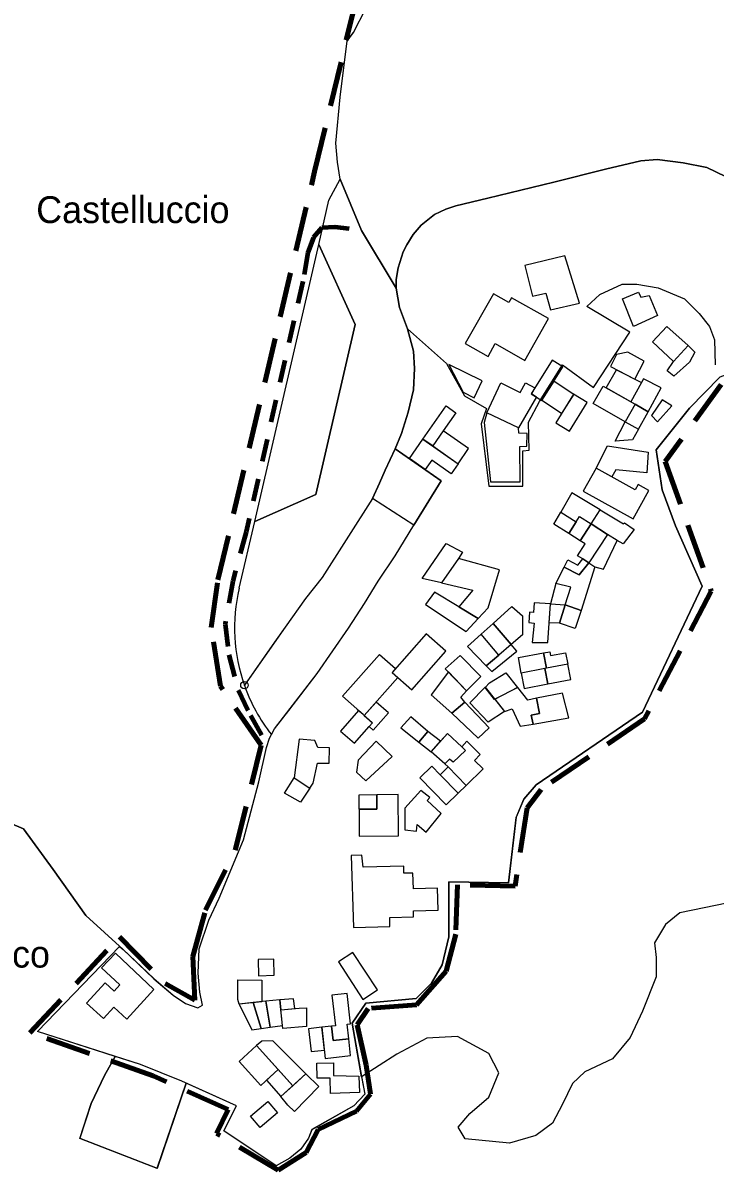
# Model space of a CAD drawing. Extents: x 650468 to 655025, y 889970 to 891591.
# Drawn here: x 654073.7 to 654331.9, y 890519.2 to 890947 of the extents above; entities that cross this region are included whole.
import ezdxf
from ezdxf.enums import TextEntityAlignment as Align

# ---------------------------------------------------------------- set-up
doc = ezdxf.new("R2010")
doc.units = 0
doc.header["$LTSCALE"] = 5.6
doc.header["$PDMODE"] = 32
doc.header["$PDSIZE"] = 2.8
doc.linetypes.add('MEDIUM_DASHED', pattern=[4.5, 3, -1.5])
doc.linetypes.add('SHORT_DASHED', pattern=[2.7, 1.5, -1.2])
for name, color, linetype, lineweight in [('1', 7, 'Continuous', 25), ('16', 7, 'Continuous', 25), ('18', 7, 'Continuous', 25), ('19', 7, 'Continuous', 25), ('35', 7, 'Continuous', 25), ('37', 7, 'Continuous', 25), ('41', 7, 'SHORT_DASHED', 80), ('7', 7, 'MEDIUM_DASHED', 100), ('8', 7, 'Continuous', 25)]:
    doc.layers.add(name, color=color, linetype=linetype, lineweight=lineweight)
doc.layers.add('60', color=7, linetype='Continuous')

msp = doc.modelspace()

# ---------------------------------------------------------------- linework, layer by layer
at = {"layer": '1'}
for p, q in [((654280.53, 890748.26), (654283.45, 890752.76)), ((654280.53, 890748.26), (654283.45, 890752.76)), ((654198.43, 890691.02), (654200.1, 890689.55)), ((654198.43, 890691.02), (654200.1, 890689.55))]:
    msp.add_line(p, q, dxfattribs=at)
for points in [[(654227.28, 890875.62), (654231.47, 890877.58), (654235.24, 890878.82), (654247.17, 890881.6), (654271.8, 890887.66), (654291.02, 890892.47), (654304.19, 890895.57), (654310.24, 890896.03), (654320, 890894.79), (654328.83, 890893.09), (654339.36, 890888.03), (654346.34, 890884.4), (654359.97, 890877.42), (654369.89, 890871.84), (654376.55, 890869.83), (654381.98, 890869.98)], [(654214.18, 890840.86), (654212.94, 890848.08), (654212.94, 890851.38), (654213.7, 890855.72), (654215.53, 890861.63), (654216.86, 890864.21), (654219.27, 890868.13), (654222.21, 890871.61), (654227.28, 890875.62)], [(654219.34, 890810.2), (654219.83, 890818.08), (654219.43, 890824.55), (654217.11, 890832.93), (654214.18, 890840.86)], [(654347.58, 890818.19), (654340.92, 890817.57), (654333.63, 890814.94), (654322.32, 890803.3), (654309.92, 890787.8)], [(654214.91, 890793.93), (654217.37, 890801.83), (654219.34, 890810.2)], [(654165.71, 890680.31), (654167.52, 890683.75), (654172.94, 890690.58), (654183.48, 890704.37), (654195.11, 890721.31), (654201.15, 890730.42), (654206.26, 890738.79), (654212.61, 890748.26), (654219.58, 890759.73), (654229.76, 890776.25), (654212.61, 890788.22), (654214.91, 890793.93)], [(654309.92, 890787.8), (654312.1, 890772.92), (654317.11, 890759.48), (654327.12, 890736.95), (654304.82, 890689.96), (654265.15, 890662.83)], [(654161.69, 890663.96), (654164.58, 890676.78), (654165.71, 890680.31)], [(654140.71, 890580.64), (654139.64, 890585.54), (654139.02, 890592.58), (654139.47, 890601.73), (654143.04, 890612.43), (654146.9, 890620.58), (654156.05, 890642.36), (654161.69, 890663.96)], [(654265.15, 890662.83), (654260.5, 890657.56), (654257.71, 890650.73), (654254.85, 890626.33), (654232.63, 890626.66), (654232.63, 890606.13)], [(654232.63, 890606.13), (654230.12, 890595.67), (654226.09, 890588.86), (654220.36, 890583.12), (654201.59, 890581.46), (654196.55, 890573.94), (654200.04, 890554.01), (654201.19, 890547.5)], [(654177.42, 890526.95), (654173.26, 890523.58), (654168.13, 890520.75), (654148.6, 890533.85), (654153.42, 890543.18), (654132.99, 890552.3), (654117.58, 890558.49), (654079.11, 890570.83), (654109.69, 890602.54), (654111.06, 890601.44), (654122.58, 890590.56), (654129.76, 890584.44)], [(654129.76, 890584.44), (654134.36, 890581.26), (654138.96, 890579.66), (654140.71, 890580.64)], [(654201.19, 890547.5), (654197.12, 890543.11), (654181.45, 890534.24)], [(654181.45, 890534.24), (654180.23, 890531.02), (654177.42, 890526.95)]]:
    msp.add_lwpolyline(points, dxfattribs=at)
for points in [[(654260.96, 890856.56), (654263.82, 890845.13), (654268.8, 890846.23), (654270.45, 890840.05), (654281.26, 890842.47), (654275.89, 890860.09)], [(654310.38, 890837.85), (654301.49, 890833.84), (654297.32, 890844.16), (654303.38, 890846.61), (654304.24, 890844.71), (654307.32, 890845.36)], [(654249.24, 890845.98), (654238.73, 890827.42), (654247.21, 890822.61), (654249.92, 890827.39), (654260.9, 890821.17), (654269.71, 890836.73), (654255.94, 890844.53), (654254.93, 890842.76)], [(654316.42, 890820.73), (654308.6, 890828.06), (654313.9, 890833.85), (654321.81, 890826.65)], [(654313.98, 890817.27), (654316.42, 890820.73), (654321.81, 890826.65), (654324.36, 890824.27), (654322.37, 890820.44), (654316.52, 890815.25)], [(654271.07, 890821.24), (654263.25, 890808.74), (654267.29, 890806.21), (654275.11, 890818.71)], [(654292.83, 890818.83), (654301.98, 890814.13), (654305.41, 890820.81), (654299.29, 890824.21), (654295.12, 890823.3)], [(654232.57, 890819.65), (654237.98, 890809.31), (654242.02, 890807.15), (654244.98, 890813.51)], [(654304.39, 890812.88), (654300.47, 890805.67), (654291.28, 890810.88), (654295.14, 890817.67)], [(654258.57, 890796.04), (654246.72, 890801.56), (654251.94, 890812.75), (654259.23, 890809.15), (654261.22, 890812.75), (654264.67, 890810.95), (654263.35, 890808.84), (654265.32, 890807.52)], [(654267.29, 890806.21), (654271.83, 890813.45), (654279.16, 890808.57), (654274.62, 890801.33)], [(654302.04, 890804.77), (654306.89, 890802.02), (654311.8, 890810.95), (654305.19, 890814.28), (654304.39, 890812.88), (654300.47, 890805.67)], [(654272.5, 890797.92), (654277.53, 890794.78), (654284.15, 890805.4), (654279.13, 890808.53)], [(654290.13, 890811.54), (654302.04, 890804.77), (654298.35, 890798.27), (654286.44, 890805.04)], [(654222.93, 890791.79), (654231.59, 890804.17), (654235.24, 890801.62), (654230.52, 890794.86), (654226.59, 890789.23)], [(654298.35, 890798.27), (654303.31, 890795.45), (654306.89, 890802.02), (654302.04, 890804.77)], [(654298.35, 890798.27), (654303.31, 890795.45), (654306.89, 890802.02), (654302.04, 890804.77)], [(654312.1, 890806.47), (654308.12, 890800.56), (654310.37, 890798.24), (654315.81, 890804.16)], [(654246.72, 890801.56), (654245.77, 890797.97), (654248.15, 890775.84), (654259.22, 890775.84), (654259.05, 890789.03), (654261.7, 890789.16), (654261.77, 890793.93), (654258.72, 890794.05), (654258.57, 890796.04)], [(654301.13, 890791.47), (654294.65, 890791.06), (654298.35, 890798.27), (654303.31, 890795.45)], [(654236.03, 890782.63), (654233.41, 890778.88), (654226.25, 890783.89), (654223.81, 890780.4), (654217.87, 890784.55), (654222.93, 890791.79)], [(654230.52, 890794.86), (654226.59, 890789.23), (654236.03, 890782.63), (654239.96, 890788.27)], [(654287.59, 890780.99), (654291.79, 890789.33), (654306.9, 890786.87), (654306.49, 890779.23), (654294.9, 890780.39), (654293.41, 890777.73)], [(654287.59, 890780.99), (654282.73, 890772.32), (654301.29, 890762.03), (654307.2, 890772.68), (654303.23, 890774.88), (654302.1, 890772.86)], [(654285.66, 890760.15), (654289.01, 890765.43), (654278.46, 890771.74), (654274.3, 890764.5), (654280.01, 890760.89), (654281.29, 890762.91)], [(654301.74, 890758.12), (654297.63, 890752.72), (654295.38, 890754.01), (654291.8, 890756.27), (654285.66, 890760.15), (654289.01, 890765.43), (654297.77, 890760.18), (654298.16, 890760.56)], [(654274.3, 890764.5), (654280.01, 890760.89), (654277.28, 890756.58), (654271.72, 890760.02)], [(654285.66, 890760.15), (654281.61, 890753.9), (654277.28, 890756.58), (654280.01, 890760.89), (654281.29, 890762.91)], [(654291.8, 890756.27), (654284.78, 890745.6), (654282.52, 890747.1), (654280.53, 890748.26), (654283.45, 890752.76), (654281.61, 890753.9), (654285.66, 890760.15)], [(654229.79, 890738.17), (654222.6, 890739.83), (654231.61, 890752.81), (654237.71, 890749.6), (654236.12, 890747.29)], [(654287.03, 890744.1), (654290.21, 890743.33), (654295.38, 890754.01), (654291.8, 890756.27), (654284.78, 890745.6)], [(654229.79, 890738.17), (654241.55, 890735.45), (654236.25, 890729.28), (654243.56, 890724.91), (654247.25, 890728.9), (654251.49, 890743.06), (654236.12, 890747.29)], [(654275.59, 890744.06), (654281.22, 890741.15), (654284.78, 890745.6), (654287.03, 890744.1), (654281.99, 890727.81), (654276.03, 890730), (654278.08, 890736.63), (654272.45, 890737.97)], [(654281.22, 890741.15), (654275.59, 890744.06), (654276.95, 890746.71), (654280.67, 890744.79), (654282.52, 890747.1), (654284.78, 890745.6)], [(654272.45, 890737.97), (654270.46, 890730.38), (654276.03, 890730), (654278.08, 890736.63)], [(654272.45, 890737.97), (654270.46, 890730.38), (654276.03, 890730), (654278.08, 890736.63)], [(654227.24, 890734.68), (654223.84, 890730.12), (654239.04, 890720.02), (654243.56, 890724.91), (654236.25, 890729.28)], [(654249.07, 890723), (654256.12, 890729.35), (654260.09, 890725.88), (654260.09, 890718.8), (654255.85, 890715.2)], [(654264.38, 890730.67), (654264.21, 890727.06), (654262.65, 890727.3), (654262.41, 890723.44), (654264.38, 890723.2), (654263.72, 890715.97), (654269.55, 890715.97), (654270.46, 890730.38)], [(654273.9, 890723.18), (654270.01, 890723.27), (654270.46, 890730.38), (654276.03, 890730)], [(654273.9, 890723.18), (654270.01, 890723.27), (654270.46, 890730.38), (654276.03, 890730)], [(654276.03, 890730), (654281.99, 890727.81), (654279.74, 890721.12), (654273.9, 890723.18)], [(654251.18, 890711.23), (654244.6, 890718.98), (654249.07, 890723), (654255.85, 890715.2)], [(654224.15, 890719.18), (654211.43, 890704.78), (654218.79, 890698.28), (654231.51, 890712.68)], [(654251.18, 890711.23), (654244.6, 890718.98), (654239.55, 890714.43), (654246.51, 890707.27)], [(654251.18, 890711.23), (654246.51, 890707.27), (654248.56, 890705.17), (654257.97, 890712.76), (654255.85, 890715.2)], [(654199.37, 890690.14), (654192.89, 890695.86), (654206.7, 890711.5), (654212.69, 890706.21), (654211.43, 890704.78), (654213.58, 890702.88), (654201.04, 890688.67)], [(654239.16, 890697.85), (654244.49, 890703.27), (654236.8, 890711.12), (654231.21, 890706.08)], [(654268.42, 890706.22), (654259.59, 890704.54), (654258.5, 890710.29), (654267.93, 890712.08), (654269.02, 890706.34)], [(654276.96, 890707.85), (654269.02, 890706.34), (654267.93, 890712.08), (654270.19, 890712.51), (654270.47, 890711.04), (654276.14, 890712.13)], [(654268.42, 890706.22), (654259.59, 890704.54), (654260.69, 890698.79), (654269.52, 890700.49)], [(654276.96, 890707.85), (654269.02, 890706.34), (654268.42, 890706.22), (654269.52, 890700.49), (654278.06, 890702.13)], [(654225.99, 890696.4), (654233.73, 890689.6), (654238.5, 890693.72), (654237.04, 890695.53), (654239.16, 890697.85), (654232.41, 890704.96)], [(654246.07, 890699.18), (654247.73, 890700.85), (654253.82, 890704.58), (654258.25, 890699.1), (654249.64, 890694.73)], [(654246.13, 890699.24), (654253.37, 890690.26), (654247.27, 890686.26), (654240.38, 890693.46)], [(654249.7, 890694.79), (654253.37, 890690.26), (654256.25, 890691.25), (654259.19, 890684.71), (654263.99, 890685.52), (654263.32, 890688.83), (654266.41, 890689.45), (654265.28, 890695.11), (654262.1, 890694.48), (654258.31, 890699.16)], [(654265.28, 890695.11), (654266.41, 890689.45), (654263.32, 890688.83), (654263.99, 890685.52), (654277.34, 890687.79), (654274.96, 890697.05)], [(654201.04, 890688.67), (654204.07, 890685.99), (654202.86, 890684.62), (654204.39, 890683.27), (654210.07, 890689.7), (654205.51, 890693.73)], [(654238.5, 890693.72), (654233.73, 890689.6), (654243.53, 890680.22), (654247.64, 890684.07)], [(654198.92, 890690.59), (654192.15, 890682.91), (654197.33, 890678.35), (654202.86, 890684.62), (654204.1, 890686.02), (654200.59, 890689.12)], [(654224.78, 890682.79), (654218.39, 890688.17), (654214.71, 890684.16), (654221.34, 890678.74)], [(654180.76, 890661.66), (654181.93, 890663.45), (654183.65, 890670.9), (654187.9, 890670.9), (654188.03, 890676.69), (654183.74, 890676.75), (654182.6, 890679.42), (654176.76, 890679.91), (654174.91, 890665.5)], [(654224.78, 890682.79), (654221.34, 890678.74), (654225.99, 890675.14), (654229.52, 890679.11)], [(654229.52, 890679.11), (654232.04, 890681.94), (654237.48, 890677.05), (654238.75, 890675.71), (654234.17, 890671.27), (654232.88, 890672.43), (654231.12, 890670.65), (654225.99, 890675.14), (654232.04, 890681.94)], [(654198.19, 890667.58), (654201.57, 890664.32), (654211.5, 890673.42), (654205.42, 890679.16), (654198.73, 890672.07)], [(654238.75, 890675.71), (654234.17, 890671.27), (654232.88, 890672.43), (654231.12, 890670.65), (654232.39, 890669.54), (654239.07, 890662.63), (654245.44, 890668.79), (654242.12, 890671.91), (654244.24, 890674.22), (654239.33, 890679.11), (654237.48, 890677.05)], [(654229.33, 890666.58), (654226.25, 890669.86), (654221.75, 890665.49), (654231.52, 890655.33), (654236.02, 890659.69)], [(654232.39, 890669.54), (654229.33, 890666.58), (654236.01, 890659.68), (654239.07, 890662.65)], [(654174.91, 890665.5), (654180.76, 890661.66), (654177.26, 890656.36), (654171.3, 890659.7)], [(654199, 890659.01), (654199.06, 890653.73), (654205.78, 890653.81), (654205.72, 890659.09)], [(654205.72, 890659.1), (654205.78, 890653.8), (654199.07, 890653.72), (654199.18, 890643.66), (654213.85, 890643.83), (654213.67, 890659.19)], [(654222.14, 890660.75), (654216.11, 890654.19), (654216.2, 890646.09), (654220.49, 890645.51), (654220.75, 890648.02), (654224.07, 890645.19), (654229.77, 890652.19), (654224.53, 890656.95), (654225.53, 890658.17)], [(654196.2, 890636.53), (654197.07, 890609.69), (654210.61, 890610.04), (654210.53, 890613.37), (654219.43, 890613.6), (654219.37, 890615.84), (654228.62, 890616.09), (654228.4, 890624.28), (654219.36, 890624.04), (654219.2, 890629.94), (654215.82, 890629.85), (654215.75, 890632.56), (654200.66, 890632.17), (654200.09, 890636.6)], [(654108.29, 890600.05), (654103.03, 890594.59), (654109.86, 890588.24), (654107.73, 890585.92), (654104.37, 890589.01), (654097.43, 890581.46), (654103.77, 890575.64), (654107.67, 890579.89), (654112.47, 890575.49), (654122.54, 890586.47)], [(654191.38, 890596.85), (654200.52, 890582.83), (654205.92, 890586.35), (654196.78, 890600.37)], [(654161.5, 890597.71), (654161.63, 890591.67), (654167.47, 890591.8), (654167.34, 890597.84)], [(654162.79, 890581.95), (654154.42, 890581.08), (654153.91, 890582.81), (654153.91, 890590.08), (654162.79, 890589.95)], [(654159.57, 890581.61), (654154.42, 890581.08), (654159.08, 890571.44), (654162.52, 890571.95)], [(654159.57, 890581.61), (654162.52, 890571.95), (654165.97, 890572.45), (654164.37, 890582.11)], [(654164.37, 890582.11), (654165.97, 890572.45), (654170.5, 890573.11), (654169.57, 890582.65)], [(654169.57, 890582.65), (654169.94, 890578.88), (654175.18, 890579.4), (654174.67, 890583.08)], [(654188.97, 890584.34), (654190.25, 890572.95), (654188.84, 890572.88), (654189.43, 890567.5), (654195.22, 890568.13), (654194.62, 890573.58), (654195.86, 890573.72), (654194.6, 890584.97)], [(654169.94, 890578.88), (654176.71, 890579.54), (654179.49, 890579.73), (654179.45, 890572.77), (654170.61, 890571.95)], [(654188.84, 890572.88), (654185.21, 890572.48), (654186.49, 890560.83), (654195.91, 890561.86), (654195.22, 890568.13), (654189.43, 890567.5)], [(654185.21, 890572.48), (654180.25, 890571.87), (654181.18, 890563.38), (654186.15, 890563.91)], [(654185.21, 890572.48), (654180.25, 890571.87), (654181.18, 890563.38), (654186.15, 890563.91)], [(654180.25, 890571.87), (654181.18, 890563.37), (654186.15, 890563.91), (654185.22, 890572.41)], [(654160.82, 890565.68), (654154.39, 890559.72), (654162.5, 890550.72), (654168.93, 890556.68)], [(654160.82, 890565.68), (654174.37, 890550.64), (654179.29, 890555.07), (654166.95, 890567.42), (654162.84, 890567.29)], [(654164.51, 890552.7), (654169.95, 890546.66), (654174.37, 890550.64), (654168.93, 890556.68)], [(654164.51, 890552.7), (654169.95, 890546.66), (654174.37, 890550.64), (654168.93, 890556.68)], [(654199.25, 890548.12), (654188.43, 890547.71), (654188.3, 890553.5), (654183.49, 890553.4), (654183.35, 890559.02), (654189.5, 890559.18), (654189.55, 890554.38), (654198.98, 890554.18)], [(654172.51, 890543.32), (654169.95, 890546.66), (654179.29, 890555.07), (654184.05, 890550.31), (654175.02, 890541.04)], [(654172.51, 890543.32), (654169.95, 890546.66), (654179.29, 890555.07), (654184.05, 890550.31), (654175.02, 890541.04)], [(654158.62, 890539.3), (654165.12, 890544.8), (654168.71, 890540.55), (654162.21, 890535.05)]]:
    msp.add_lwpolyline(points, close=True, dxfattribs=at)
at = {"layer": '16'}
msp.add_lwpolyline([(654219.58, 890759.73), (654204.05, 890769.68), (654206.68, 890775.42), (654208.8, 890780.19), (654212.61, 890788.22), (654229.76, 890776.25)], close=True, dxfattribs=at)
for points in [[(654132.99, 890552.3), (654117.58, 890558.49), (654108.06, 890561.55), (654104.11, 890554.41), (654099.12, 890543.97), (654094.92, 890531.01)], [(654094.92, 890531.01), (654123.75, 890519.82), (654134.64, 890551.56), (654132.99, 890552.3)]]:
    msp.add_lwpolyline(points, dxfattribs=at)
at = {"layer": '18'}
msp.add_lwpolyline([(654197.67, 890834.54), (654183.02, 890771.19), (654160.16, 890761.08), (654184.05, 890864.38)], close=True, dxfattribs=at)
for points in [[(654166.4, 890681.61), (654167.52, 890683.75), (654183.48, 890704.37), (654195.11, 890721.31), (654201.15, 890730.42), (654206.26, 890738.79), (654212.61, 890748.26), (654219.58, 890759.73), (654204.05, 890769.68), (654185.31, 890740.14)], [(654185.31, 890740.14), (654179.11, 890732.3), (654171.5, 890721.68), (654156.34, 890700.02)]]:
    msp.add_lwpolyline(points, dxfattribs=at)
msp.add_arc((654215.65, 890720.46), 62.73, 199.0234, 218.2702, dxfattribs=at)
msp.add_point((654156.34, 890700.02), dxfattribs=at)
at = {"layer": '19'}
msp.add_line((654167.6, 890716.1), (654156.34, 890700.01), dxfattribs=at)
for points in [[(654212.94, 890851.38), (654212.94, 890848.08), (654199.97, 890869.6), (654192.08, 890888.74), (654191.09, 890895.12), (654190.43, 890902.13), (654192.08, 890919.36), (654194.7, 890940.28), (654197, 890943.46), (654201.61, 890952.4)], [(654417.62, 890950.54), (654399.53, 890902.06), (654391.04, 890877.22), (654388.18, 890871.69), (654381.98, 890869.98), (654376.55, 890869.83), (654369.89, 890871.84), (654359.97, 890877.42), (654346.34, 890884.4), (654339.36, 890888.03), (654328.83, 890893.09), (654320, 890894.79), (654310.24, 890896.03), (654304.19, 890895.57), (654291.02, 890892.47), (654271.8, 890887.66), (654247.17, 890881.6), (654235.24, 890878.82), (654231.47, 890877.58)], [(654154.4, 890736.14), (654160.16, 890761.07), (654183.02, 890771.18), (654197.67, 890834.53), (654184.05, 890864.37), (654187.87, 890880.92), (654192.08, 890888.73), (654199.97, 890869.59), (654212.94, 890848.07), (654214.18, 890840.85), (654217.11, 890832.92), (654219.43, 890824.54)], [(654231.47, 890877.58), (654227.28, 890875.62), (654222.21, 890871.61)], [(654222.21, 890871.61), (654219.27, 890868.13), (654216.86, 890864.21), (654215.53, 890861.63)], [(654215.53, 890861.63), (654213.7, 890855.72), (654212.94, 890851.38)], [(654219.43, 890824.54), (654219.83, 890818.07), (654219.34, 890810.19)], [(654219.34, 890810.19), (654217.37, 890801.82), (654214.91, 890793.92), (654212.61, 890788.21), (654208.8, 890780.18), (654206.68, 890775.41), (654204.05, 890769.67), (654185.31, 890740.13)], [(654185.31, 890740.13), (654179.11, 890732.29), (654171.5, 890721.67), (654167.6, 890716.1)]]:
    msp.add_lwpolyline(points, dxfattribs=at)
msp.add_arc((654215.63, 890721.3), 63, 166.3715, 199.754, dxfattribs=at)
at = {"layer": '35'}
msp.add_lwpolyline([(654372.59, 890626.21), (654318.79, 890615.05), (654313.35, 890610.75), (654309.34, 890603.88), (654309.92, 890598.44), (654309.92, 890591.28), (654304.77, 890578.4), (654300.19, 890568.66), (654293.6, 890560.65), (654283.3, 890555.78), (654278.72, 890551.48), (654275, 890543.75), (654271.28, 890536.6), (654264.99, 890532.02), (654255.26, 890529.15), (654238.66, 890530.87), (654236.08, 890535.16), (654240.37, 890540.32), (654247.53, 890546.33), (654251.25, 890555.49), (654247.53, 890562.65), (654235.8, 890568.95), (654224.35, 890568.38), (654213.19, 890562.37), (654200.04, 890554), (654196.55, 890573.93), (654201.59, 890581.45), (654220.36, 890583.11), (654226.09, 890588.85), (654230.12, 890595.66), (654232.63, 890606.12), (654232.63, 890616.39), (654232.63, 890626.65), (654254.85, 890626.32), (654257.71, 890650.72), (654260.5, 890657.55), (654265.15, 890662.82), (654304.82, 890689.95), (654327.12, 890736.94), (654317.11, 890759.47), (654312.1, 890772.91), (654309.92, 890787.79), (654322.32, 890803.29), (654333.63, 890814.93)], dxfattribs=at)
at = {"layer": '37'}
for points in [[(654154.4, 890736.15), (654160.16, 890761.07), (654184.05, 890864.37), (654187.87, 890880.92), (654192.08, 890888.73), (654191.09, 890895.11), (654190.43, 890902.12), (654192.08, 890919.35), (654194.7, 890940.27), (654197, 890943.45), (654201.61, 890952.39), (654189.01, 890960.03), (654162.37, 890950.57), (654152.28, 890979.05), (654174.81, 890986.42), (654182.54, 890982.69), (654170.7, 891003.42)], [(653959.44, 890683.82), (653977.03, 890679.77), (654009.33, 890666.64), (654030.52, 890657.56), (654054.75, 890654.53), (654073.92, 890646.45), (654085.02, 890631.3), (654097.14, 890614.13), (654111.06, 890601.43), (654122.58, 890590.55), (654129.76, 890584.43)], [(654161.69, 890663.95), (654164.58, 890676.77), (654165.71, 890680.3), (654166.4, 890681.61)], [(654140.71, 890580.63), (654139.64, 890585.53), (654139.02, 890592.57), (654139.47, 890601.72), (654143.04, 890612.42), (654146.9, 890620.57), (654156.05, 890642.35), (654161.69, 890663.95)], [(654111.06, 890601.43), (654097.14, 890614.13), (654085.02, 890631.3), (654073.92, 890646.45), (654054.75, 890654.53)], [(654372.59, 890626.21), (654318.79, 890615.05), (654313.35, 890610.75), (654309.34, 890603.88), (654309.92, 890598.44), (654309.92, 890591.28), (654304.77, 890578.4), (654300.19, 890568.66), (654293.6, 890560.65), (654283.3, 890555.78), (654278.72, 890551.48), (654275, 890543.75), (654271.28, 890536.6), (654264.99, 890532.02), (654255.26, 890529.15), (654238.66, 890530.87), (654236.08, 890535.16), (654240.37, 890540.32), (654247.53, 890546.33), (654251.25, 890555.49), (654247.53, 890562.65), (654235.8, 890568.95), (654224.35, 890568.38), (654213.19, 890562.37), (654200.04, 890554), (654201.19, 890547.49)], [(654177.42, 890526.94), (654173.26, 890523.57), (654168.13, 890520.74), (654148.6, 890533.84), (654153.42, 890543.17), (654134.64, 890551.56), (654123.75, 890519.81), (654094.92, 890531), (654099.12, 890543.96), (654104.11, 890554.4), (654108.06, 890561.54), (654079.11, 890570.82), (654109.69, 890602.53), (654111.06, 890601.43)], [(654129.76, 890584.43), (654134.36, 890581.25), (654138.96, 890579.65), (654140.71, 890580.63)], [(654201.19, 890547.49), (654197.12, 890543.1), (654181.45, 890534.23)], [(654181.45, 890534.23), (654180.23, 890531.01), (654177.42, 890526.94)]]:
    msp.add_lwpolyline(points, dxfattribs=at)
for centre, radius, start, end in [((654215.63, 890721.3), 63, 166.3715, 199.754), ((654215.65, 890720.46), 62.73, 199.0264, 218.2702)]:
    msp.add_arc(centre, radius, start, end, dxfattribs=at)
at = {"layer": '41'}
msp.add_lwpolyline([(654195.39, 890870.16), (654190.09, 890870.85), (654185.26, 890870.53), (654182.04, 890866.99), (654180, 890861.45), (654178.14, 890850.6), (654156.95, 890757.21), (654151.99, 890738.82), (654149.1, 890722.76), (654150.53, 890711.37), (654153.99, 890698.12), (654158.55, 890688.68), (654163.7, 890679.54)], dxfattribs=at)
at = {"layer": '7'}
for points in [[(654150.33, 890541.8), (654122.3, 890554.3), (654076.35, 890570.4), (654109.74, 890606.13), (654126.72, 890588.79), (654137.85, 890582.59), (654137.14, 890598.86), (654141.85, 890616.07), (654152.92, 890638.46), (654162.58, 890677.6), (654147.42, 890699.63), (654143.92, 890721.53), (654146.47, 890739.35), (654182.51, 890891.6), (654197.39, 890953.2)], [(654334.19, 890812.15), (654313.32, 890783.38), (654330.48, 890735.12), (654305.6, 890687.5), (654266.96, 890661.1), (654261.78, 890654.26), (654257.3, 890625.03), (654235.86, 890625.5), (654235.15, 890607.11), (654231.64, 890593.4), (654220.48, 890580.85), (654202.55, 890579.45), (654198.36, 890573.31), (654201.7, 890558.31), (654203.35, 890547.46), (654198.16, 890541.1), (654183.79, 890534.26), (654179.31, 890525.77), (654168.95, 890519.17), (654145.86, 890532.85), (654150.33, 890541.8)]]:
    msp.add_lwpolyline(points, dxfattribs=at)
at = {"layer": '8'}
msp.add_lwpolyline([(654339.36, 890888.03), (654328.83, 890893.09), (654320, 890894.79), (654310.24, 890896.03), (654304.19, 890895.57), (654291.02, 890892.47), (654271.8, 890887.66), (654247.17, 890881.6), (654235.24, 890878.82), (654231.47, 890877.58), (654227.28, 890875.62), (654222.21, 890871.61), (654219.27, 890868.13), (654216.86, 890864.21), (654215.53, 890861.63), (654213.7, 890855.72), (654212.94, 890851.38), (654212.94, 890848.08), (654214.18, 890840.86), (654217.11, 890832.93), (654231.75, 890819.94), (654238.44, 890807.98), (654246.57, 890803.2), (654244.66, 890797.46), (654247.53, 890774.25), (654260.2, 890774.25), (654260.2, 890787.41), (654262.59, 890787.65), (654262.35, 890798.17), (654266.42, 890805.83), (654275.02, 890819.46), (654286.5, 890811.09), (654300.12, 890831.66), (654284.11, 890841.23), (654288.89, 890845.78), (654297.26, 890849.61), (654302.75, 890849.61), (654310.64, 890848.17), (654320.45, 890844.1), (654325.95, 890838.61), (654329.77, 890833.82), (654331.69, 890828.8), (654331.93, 890819.47)], dxfattribs=at)

# ---------------------------------------------------------------- texts
at = {"layer": '60'}
for s, p in [('Castelluccio', (654114.72, 890872.37)), ("Ca'  di  Cecco", (654042.38, 890594.69))]:
    msp.add_text(s, height=10, dxfattribs=at).set_placement(p, align=Align.CENTER)

doc.saveas('drawing.dxf')
